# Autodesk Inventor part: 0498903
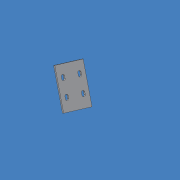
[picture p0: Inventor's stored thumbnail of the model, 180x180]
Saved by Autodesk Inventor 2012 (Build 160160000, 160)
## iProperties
Company: CAD-Verlag
Shininess: 64.0
Length Units: 11269
Angle Units: 11279
Time Units: 11290
Mass Units: 11283
Length Display Precision: 3
Angle Display Precision: 2
Compacted: True
Part Number: 0498903
Document SubType Name: Modeling
Created: 2004-09
Material: Standard
Designer: Greiling
Manufacturer: Standard
Standards Organization: Custom
Density: 1 g/cm^3
Density: 0.0
Volumn: 0.0
Area: 0.0
PropertySet Name: Model Information
Control State: 0
Master: False
Checked Out: False
Author: Jürgen Kronas
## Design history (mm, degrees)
sketch "Skizze1"
  geometry: L1 (0, 254.808)-(0, -32.565) reference; L2 (-12.1, 0)-(157.3, 0) reference; L3 (-12.1, 0)-(157.3, 0) reference; L4 (0, -32.565)-(0, 254.808) reference; L5 (1, 181)-(1, 0); L6 (1, 0)-(121, 0); L7 (121, 0)-(121, 181); L8 (121, 181)-(1, 181); L9 (61, 193.228)-(61, -12.038); L10 (14.39, 130)-(37.61, 130); L11 (96, 72.542)-(96, 37.458); L12 (84.39, 130)-(107.61, 130); L13 (96, 147.542)-(96, 112.458); L14 (87.324, 49.5)-(104.676, 49.5); L15 (26, 147.542)-(26, 112.458); L16 (17.324, 135.5)-(34.676, 135.5); L17 (17.324, 124.5)-(34.676, 124.5); L18 (87.324, 124.5)-(104.676, 124.5); L19 (87.324, 135.5)-(104.676, 135.5); L20 (87.324, 60.5)-(104.676, 60.5); L21 (84.39, 55)-(107.61, 55); L22 (26, 72.542)-(26, 37.458); L23 (17.324, 49.5)-(34.676, 49.5); L24 (17.324, 60.5)-(34.676, 60.5); L25 (14.39, 55)-(37.61, 55); L26 (0, 0)-(1, 0); L27 (0, 0)-(1, 0); L28 (103, 130)-(103, 124.5); L29 (103, 130)-(103, 135.5); L30 (89, 130)-(89, 135.5); L31 (33, 130)-(33, 135.5); L32 (0, 0)-(1, 0); L33 (89, 55)-(89, 49.5); L34 (0, 0)-(1, 0); L35 (89, 55)-(89, 60.5); L36 (0, 0)-(1, 0); L37 (103, 55)-(103, 49.5); L38 (103, 55)-(103, 60.5); L39 (19, 130)-(19, 135.5); L40 (19, 130)-(19, 124.5); L41 (0, 0)-(1, 0); L42 (19, 55)-(19, 49.5); L43 (0, 0)-(1, 0); L44 (19, 55)-(19, 60.5); L45 (0, 0)-(1, 0); L46 (33, 55)-(33, 60.5); L47 (33, 130)-(33, 124.5); L48 (89, 130)-(89, 124.5); L49 (33, 55)-(33, 49.5); A1 r 7 centre (96, 49.5) between (89, 49.5) and (103, 49.5); A2 r 7 centre (96, 60.5) between (103, 60.5) and (89, 60.5); A3 r 7 centre (26, 135.5) between (33, 135.5) and (19, 135.5); A4 r 7 centre (26, 49.5) between (19, 49.5) and (33, 49.5); A5 r 7 centre (26, 124.5) between (19, 124.5) and (33, 124.5); A6 r 7 centre (26, 60.5) between (33, 60.5) and (19, 60.5); A7 r 7 centre (96, 124.5) between (89, 124.5) and (103, 124.5); A8 r 7 centre (96, 135.5) between (103, 135.5) and (89, 135.5)
  constraints: 90 end point, 37 point on line, 16 point on circle, 8 centre point, 8 midpoint
extrude "Extrusion1" new body sketch "Skizze1" distance "d0" = 10; taper "d1" = 0 deg
node "Volumenkörper1"
node "Volumenkörpern"
node "Oberflächenkörpern"
